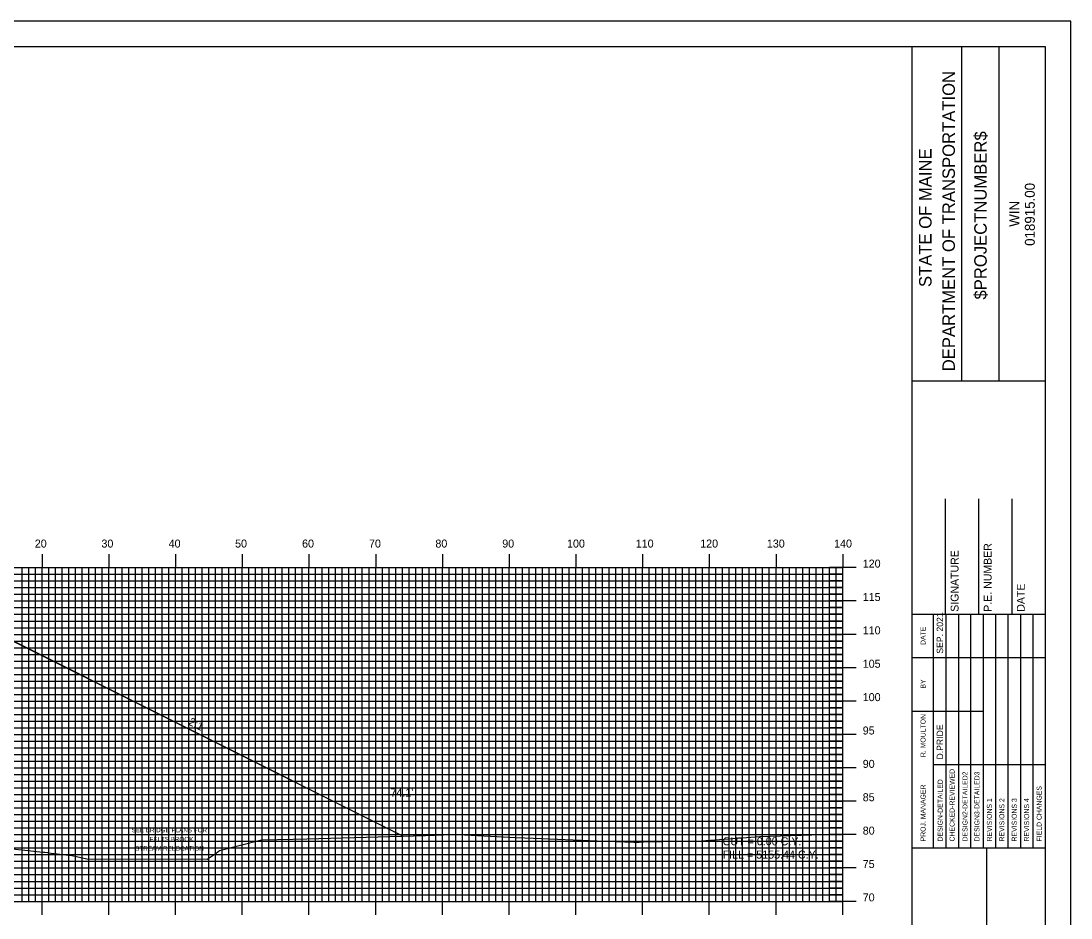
# Model space of a CAD drawing. Extents: x 857897 to 858240, y 364765 to 364985.
# Drawn here: x 858079.7 to 858237, y 364850.8 to 364985.2 of the extents above; entities that cross this region are included whole.
import ezdxf

# ---------------------------------------------------------------- set-up
doc = ezdxf.new("R2010")
doc.units = 0
for name, color, linetype in [('ANNOTATION', 7, 'Continuous'), ('BORDER', 7, 'Continuous'), ('D_Roadway_Centerline', 7, 'Continuous'), ('D_Roadway_SlopeLines', 7, 'Continuous'), ('D_Text_Standard', 7, 'Continuous'), ('H_V ANNOTATION', 7, 'Continuous'), ('MAJOR', 7, 'Continuous'), ('MINOR', 7, 'Continuous'), ('PLOT BOUNDARY', 7, 'Continuous'), ('S_Roadway_Centerline', 7, 'Continuous')]:
    doc.layers.add(name, color=color, linetype=linetype)

msp = doc.modelspace()

# ---------------------------------------------------------------- linework, layer by layer
at = {"layer": 'BORDER'}
for p, q in [((858213.22, 364771.3), (858213.22, 364981.3)), ((858220.68, 364931.3), (858220.68, 364981.3)), ((858226.27, 364931.3), (858226.27, 364981.3)), ((858213.22, 364931.29), (858233.22, 364931.29)), ((858218.22, 364896.31), (858218.22, 364913.6)), ((858223.22, 364896.31), (858223.22, 364913.6)), ((858228.22, 364896.31), (858228.22, 364913.6)), ((858213.22, 364896.31), (858233.22, 364896.31)), ((858213.22, 364861.31), (858233.22, 364861.31)), ((858224.4, 364791.31), (858224.4, 364861.31))]:
    msp.add_line(p, q, dxfattribs=at)
msp.add_lwpolyline([(857913.22, 364771.3), (858233.22, 364771.3), (858233.22, 364981.3), (857913.22, 364981.3)], close=True, dxfattribs=at)
for points in [[(858216.45, 364889.81), (858216.45, 364896.31)], [(858218.32, 364861.31), (858218.32, 364896.31)], [(858220.18, 364896.31), (858220.18, 364861.31)], [(858222.04, 364861.31), (858222.04, 364896.31)], [(858223.91, 364861.31), (858223.91, 364896.31)], [(858225.77, 364861.31), (858225.77, 364896.31)], [(858227.63, 364861.31), (858227.63, 364896.31)], [(858229.5, 364861.31), (858229.5, 364896.31)], [(858231.36, 364861.31), (858231.36, 364896.31)], [(858216.45, 364861.31), (858216.45, 364894.9)], [(858213.22, 364889.81), (858233.22, 364889.81)], [(858213.22, 364881.81), (858216.45, 364881.81)], [(858216.45, 364881.81), (858223.9, 364881.81)], [(858216.45, 364873.81), (858233.22, 364873.81)]]:
    msp.add_lwpolyline(points, dxfattribs=at)
at = {"layer": 'D_Roadway_Centerline'}
msp.add_lwpolyline([(857981.97, 364866.56), (858035.61, 364893.37), (858040.82, 364895.98), (858043.82, 364896.04), (858048.82, 364896.14), (858062.82, 364895.3), (858070.82, 364894.82), (858073.82, 364894.64), (858079.5, 364891.8), (858136.93, 364863.09)], dxfattribs=at)
at = {"layer": 'D_Roadway_SlopeLines'}
msp.add_lwpolyline([(858073.82, 364894.64), (858136.93, 364863.09)], dxfattribs=at)
at = {"layer": 'MAJOR'}
for p, q in [((858082.82, 364905.31), (858082.82, 364903.3)), ((858092.82, 364905.31), (858092.82, 364903.3)), ((858102.82, 364905.31), (858102.82, 364903.3)), ((858112.82, 364905.31), (858112.82, 364903.3)), ((858122.82, 364905.31), (858122.82, 364903.3)), ((858132.82, 364905.31), (858132.82, 364903.3)), ((858142.82, 364905.31), (858142.82, 364903.3)), ((858152.82, 364905.31), (858152.82, 364903.3)), ((858162.82, 364905.31), (858162.82, 364903.3)), ((858172.82, 364905.31), (858172.82, 364903.3)), ((858182.82, 364905.31), (858182.82, 364903.3)), ((858192.82, 364905.31), (858192.82, 364903.3)), ((858202.82, 364905.31), (858202.82, 364903.3)), ((857922.82, 364903.3), (858202.82, 364903.3)), ((857922.82, 364903.3), (858202.82, 364903.3)), ((858082.82, 364853.3), (858082.82, 364903.3)), ((858092.82, 364853.3), (858092.82, 364903.3)), ((858102.82, 364853.3), (858102.82, 364903.3)), ((858112.82, 364853.3), (858112.82, 364903.3)), ((858122.82, 364853.3), (858122.82, 364903.3)), ((858132.82, 364853.3), (858132.82, 364903.3)), ((858142.82, 364853.3), (858142.82, 364903.3)), ((858152.82, 364853.3), (858152.82, 364903.3)), ((858162.82, 364853.3), (858162.82, 364903.3)), ((858172.82, 364853.3), (858172.82, 364903.3)), ((858182.82, 364853.3), (858182.82, 364903.3)), ((858192.82, 364853.3), (858192.82, 364903.3)), ((858204.82, 364903.3), (858200.82, 364903.3)), ((858202.82, 364853.3), (858202.82, 364903.3)), ((858202.82, 364853.3), (858202.82, 364903.3)), ((857922.82, 364898.3), (858202.82, 364898.3)), ((858204.82, 364898.3), (858200.82, 364898.3)), ((857922.82, 364893.3), (858202.82, 364893.3)), ((858204.82, 364893.3), (858200.82, 364893.3)), ((857922.82, 364888.3), (858202.82, 364888.3)), ((858204.82, 364888.3), (858200.82, 364888.3)), ((857922.82, 364883.3), (858202.82, 364883.3)), ((858204.82, 364883.3), (858200.82, 364883.3)), ((857922.82, 364878.3), (858202.82, 364878.3)), ((858204.82, 364878.3), (858200.82, 364878.3)), ((857922.82, 364873.3), (858202.82, 364873.3)), ((858204.82, 364873.3), (858200.82, 364873.3)), ((857922.82, 364868.3), (858202.82, 364868.3)), ((858204.82, 364868.3), (858200.82, 364868.3)), ((857922.82, 364863.3), (858202.82, 364863.3)), ((858204.82, 364863.3), (858200.82, 364863.3)), ((857922.82, 364858.3), (858202.82, 364858.3)), ((858204.82, 364858.3), (858200.82, 364858.3)), ((857922.82, 364853.3), (858202.82, 364853.3)), ((857922.82, 364853.3), (858202.82, 364853.3)), ((858082.82, 364851.3), (858082.82, 364853.3)), ((858092.82, 364851.3), (858092.82, 364853.3)), ((858102.82, 364851.3), (858102.82, 364853.3)), ((858112.82, 364851.3), (858112.82, 364853.3)), ((858122.82, 364851.3), (858122.82, 364853.3)), ((858132.82, 364851.3), (858132.82, 364853.3)), ((858142.82, 364851.3), (858142.82, 364853.3)), ((858152.82, 364851.3), (858152.82, 364853.3)), ((858162.82, 364851.3), (858162.82, 364853.3)), ((858172.82, 364851.3), (858172.82, 364853.3)), ((858182.82, 364851.3), (858182.82, 364853.3)), ((858192.82, 364851.3), (858192.82, 364853.3)), ((858204.82, 364853.3), (858200.82, 364853.3)), ((858202.82, 364851.3), (858202.82, 364853.3))]:
    msp.add_line(p, q, dxfattribs=at)
at = {"layer": 'MINOR'}
for p, q in [((858079.82, 364853.3), (858079.82, 364903.3)), ((858080.82, 364853.3), (858080.82, 364903.3)), ((858081.82, 364853.3), (858081.82, 364903.3)), ((858083.82, 364853.3), (858083.82, 364903.3)), ((858084.82, 364853.3), (858084.82, 364903.3)), ((858085.82, 364853.3), (858085.82, 364903.3)), ((858086.82, 364853.3), (858086.82, 364903.3)), ((858087.82, 364853.3), (858087.82, 364903.3)), ((858088.82, 364853.3), (858088.82, 364903.3)), ((858089.82, 364853.3), (858089.82, 364903.3)), ((858090.82, 364853.3), (858090.82, 364903.3)), ((858091.82, 364853.3), (858091.82, 364903.3)), ((858093.82, 364853.3), (858093.82, 364903.3)), ((858094.82, 364853.3), (858094.82, 364903.3)), ((858095.82, 364853.3), (858095.82, 364903.3)), ((858096.82, 364853.3), (858096.82, 364903.3)), ((858097.82, 364853.3), (858097.82, 364903.3)), ((858098.82, 364853.3), (858098.82, 364903.3)), ((858099.82, 364853.3), (858099.82, 364903.3)), ((858100.82, 364853.3), (858100.82, 364903.3)), ((858101.82, 364853.3), (858101.82, 364903.3)), ((858103.82, 364853.3), (858103.82, 364903.3)), ((858104.82, 364853.3), (858104.82, 364903.3)), ((858105.82, 364853.3), (858105.82, 364903.3)), ((858106.82, 364853.3), (858106.82, 364903.3)), ((858107.82, 364853.3), (858107.82, 364903.3)), ((858108.82, 364853.3), (858108.82, 364903.3)), ((858109.82, 364853.3), (858109.82, 364903.3)), ((858110.82, 364853.3), (858110.82, 364903.3)), ((858111.82, 364853.3), (858111.82, 364903.3)), ((858113.82, 364853.3), (858113.82, 364903.3)), ((858114.82, 364853.3), (858114.82, 364903.3)), ((858115.82, 364853.3), (858115.82, 364903.3)), ((858116.82, 364853.3), (858116.82, 364903.3)), ((858117.82, 364853.3), (858117.82, 364903.3)), ((858118.82, 364853.3), (858118.82, 364903.3)), ((858119.82, 364853.3), (858119.82, 364903.3)), ((858120.82, 364853.3), (858120.82, 364903.3)), ((858121.82, 364853.3), (858121.82, 364903.3)), ((858123.82, 364853.3), (858123.82, 364903.3)), ((858124.82, 364853.3), (858124.82, 364903.3)), ((858125.82, 364853.3), (858125.82, 364903.3)), ((858126.82, 364853.3), (858126.82, 364903.3)), ((858127.82, 364853.3), (858127.82, 364903.3)), ((858128.82, 364853.3), (858128.82, 364903.3)), ((858129.82, 364853.3), (858129.82, 364903.3)), ((858130.82, 364853.3), (858130.82, 364903.3)), ((858131.82, 364853.3), (858131.82, 364903.3)), ((858133.82, 364853.3), (858133.82, 364903.3)), ((858134.82, 364853.3), (858134.82, 364903.3)), ((858135.82, 364853.3), (858135.82, 364903.3)), ((858136.82, 364853.3), (858136.82, 364903.3)), ((858137.82, 364853.3), (858137.82, 364903.3)), ((858138.82, 364853.3), (858138.82, 364903.3)), ((858139.82, 364853.3), (858139.82, 364903.3)), ((858140.82, 364853.3), (858140.82, 364903.3)), ((858141.82, 364853.3), (858141.82, 364903.3)), ((858143.82, 364853.3), (858143.82, 364903.3)), ((858144.82, 364853.3), (858144.82, 364903.3)), ((858145.82, 364853.3), (858145.82, 364903.3)), ((858146.82, 364853.3), (858146.82, 364903.3)), ((858147.82, 364853.3), (858147.82, 364903.3)), ((858148.82, 364853.3), (858148.82, 364903.3)), ((858149.82, 364853.3), (858149.82, 364903.3)), ((858150.82, 364853.3), (858150.82, 364903.3)), ((858151.82, 364853.3), (858151.82, 364903.3)), ((858153.82, 364853.3), (858153.82, 364903.3)), ((858154.82, 364853.3), (858154.82, 364903.3)), ((858155.82, 364853.3), (858155.82, 364903.3)), ((858156.82, 364853.3), (858156.82, 364903.3)), ((858157.82, 364853.3), (858157.82, 364903.3)), ((858158.82, 364853.3), (858158.82, 364903.3)), ((858159.82, 364853.3), (858159.82, 364903.3)), ((858160.82, 364853.3), (858160.82, 364903.3)), ((858161.82, 364853.3), (858161.82, 364903.3)), ((858163.82, 364853.3), (858163.82, 364903.3)), ((858164.82, 364853.3), (858164.82, 364903.3)), ((858165.82, 364853.3), (858165.82, 364903.3)), ((858166.82, 364853.3), (858166.82, 364903.3)), ((858167.82, 364853.3), (858167.82, 364903.3)), ((858168.82, 364853.3), (858168.82, 364903.3)), ((858169.82, 364853.3), (858169.82, 364903.3)), ((858170.82, 364853.3), (858170.82, 364903.3)), ((858171.82, 364853.3), (858171.82, 364903.3)), ((858173.82, 364853.3), (858173.82, 364903.3)), ((858174.82, 364853.3), (858174.82, 364903.3)), ((858175.82, 364853.3), (858175.82, 364903.3)), ((858176.82, 364853.3), (858176.82, 364903.3)), ((858177.82, 364853.3), (858177.82, 364903.3)), ((858178.82, 364853.3), (858178.82, 364903.3)), ((858179.82, 364853.3), (858179.82, 364903.3)), ((858180.82, 364853.3), (858180.82, 364903.3)), ((858181.82, 364853.3), (858181.82, 364903.3)), ((858183.82, 364853.3), (858183.82, 364903.3)), ((858184.82, 364853.3), (858184.82, 364903.3)), ((858185.82, 364853.3), (858185.82, 364903.3)), ((858186.82, 364853.3), (858186.82, 364903.3)), ((858187.82, 364853.3), (858187.82, 364903.3)), ((858188.82, 364853.3), (858188.82, 364903.3)), ((858189.82, 364853.3), (858189.82, 364903.3)), ((858190.82, 364853.3), (858190.82, 364903.3)), ((858191.82, 364853.3), (858191.82, 364903.3)), ((858193.82, 364853.3), (858193.82, 364903.3)), ((858194.82, 364853.3), (858194.82, 364903.3)), ((858195.82, 364853.3), (858195.82, 364903.3)), ((858196.82, 364853.3), (858196.82, 364903.3)), ((858197.82, 364853.3), (858197.82, 364903.3)), ((858198.82, 364853.3), (858198.82, 364903.3)), ((858199.82, 364853.3), (858199.82, 364903.3)), ((858200.82, 364853.3), (858200.82, 364903.3)), ((858201.82, 364853.3), (858201.82, 364903.3)), ((857922.82, 364902.3), (858202.82, 364902.3)), ((857922.82, 364901.3), (858202.82, 364901.3)), ((858202.82, 364902.3), (858200.82, 364902.3)), ((858202.82, 364901.3), (858200.82, 364901.3)), ((857922.82, 364900.3), (858202.82, 364900.3)), ((858202.82, 364900.3), (858200.82, 364900.3)), ((857922.82, 364899.3), (858202.82, 364899.3)), ((858202.82, 364899.3), (858200.82, 364899.3)), ((857922.82, 364897.3), (858202.82, 364897.3)), ((857922.82, 364896.3), (858202.82, 364896.3)), ((858202.82, 364897.3), (858200.82, 364897.3)), ((858202.82, 364896.3), (858200.82, 364896.3)), ((857922.82, 364895.3), (858202.82, 364895.3)), ((858202.82, 364895.3), (858200.82, 364895.3)), ((857922.82, 364894.3), (858202.82, 364894.3)), ((858202.82, 364894.3), (858200.82, 364894.3)), ((857922.82, 364892.3), (858202.82, 364892.3)), ((858202.82, 364892.3), (858200.82, 364892.3)), ((857922.82, 364891.3), (858202.82, 364891.3)), ((857922.82, 364890.3), (858202.82, 364890.3)), ((858202.82, 364891.3), (858200.82, 364891.3)), ((858202.82, 364890.3), (858200.82, 364890.3)), ((857922.82, 364889.3), (858202.82, 364889.3)), ((858202.82, 364889.3), (858200.82, 364889.3)), ((857922.82, 364887.3), (858202.82, 364887.3)), ((858202.82, 364887.3), (858200.82, 364887.3)), ((857922.82, 364886.3), (858202.82, 364886.3)), ((857922.82, 364885.3), (858202.82, 364885.3)), ((858202.82, 364886.3), (858200.82, 364886.3)), ((858202.82, 364885.3), (858200.82, 364885.3)), ((857922.82, 364884.3), (858202.82, 364884.3)), ((858202.82, 364884.3), (858200.82, 364884.3)), ((857922.82, 364882.3), (858202.82, 364882.3)), ((858202.82, 364882.3), (858200.82, 364882.3)), ((857922.82, 364881.3), (858202.82, 364881.3)), ((858202.82, 364881.3), (858200.82, 364881.3)), ((857922.82, 364880.3), (858202.82, 364880.3)), ((857922.82, 364879.3), (858202.82, 364879.3)), ((858202.82, 364880.3), (858200.82, 364880.3)), ((858202.82, 364879.3), (858200.82, 364879.3)), ((857922.82, 364877.3), (858202.82, 364877.3)), ((857922.82, 364876.3), (858202.82, 364876.3)), ((858202.82, 364877.3), (858200.82, 364877.3)), ((858202.82, 364876.3), (858200.82, 364876.3)), ((857922.82, 364875.3), (858202.82, 364875.3)), ((857922.82, 364874.3), (858202.82, 364874.3)), ((858202.82, 364875.3), (858200.82, 364875.3)), ((858202.82, 364874.3), (858200.82, 364874.3)), ((857922.82, 364872.3), (858202.82, 364872.3)), ((857922.82, 364871.3), (858202.82, 364871.3)), ((858202.82, 364872.3), (858200.82, 364872.3)), ((858202.82, 364871.3), (858200.82, 364871.3)), ((857922.82, 364870.3), (858202.82, 364870.3)), ((858202.82, 364870.3), (858200.82, 364870.3)), ((857922.82, 364869.3), (858202.82, 364869.3)), ((858202.82, 364869.3), (858200.82, 364869.3)), ((857922.82, 364867.3), (858202.82, 364867.3)), ((858202.82, 364867.3), (858200.82, 364867.3)), ((857922.82, 364866.3), (858202.82, 364866.3)), ((857922.82, 364865.3), (858202.82, 364865.3)), ((858202.82, 364866.3), (858200.82, 364866.3)), ((858202.82, 364865.3), (858200.82, 364865.3)), ((857922.82, 364864.3), (858202.82, 364864.3)), ((858202.82, 364864.3), (858200.82, 364864.3)), ((857922.82, 364862.3), (858202.82, 364862.3)), ((858202.82, 364862.3), (858200.82, 364862.3)), ((857922.82, 364861.3), (858202.82, 364861.3)), ((857922.82, 364860.3), (858202.82, 364860.3)), ((858202.82, 364861.3), (858200.82, 364861.3)), ((858202.82, 364860.3), (858200.82, 364860.3)), ((857922.82, 364859.3), (858202.82, 364859.3)), ((858202.82, 364859.3), (858200.82, 364859.3)), ((857922.82, 364857.3), (858202.82, 364857.3)), ((858202.82, 364857.3), (858200.82, 364857.3)), ((857922.82, 364856.3), (858202.82, 364856.3)), ((858202.82, 364856.3), (858200.82, 364856.3)), ((857922.82, 364855.3), (858202.82, 364855.3)), ((857922.82, 364854.3), (858202.82, 364854.3)), ((858202.82, 364855.3), (858200.82, 364855.3)), ((858202.82, 364854.3), (858200.82, 364854.3))]:
    msp.add_line(p, q, dxfattribs=at)
at = {"layer": 'PLOT BOUNDARY'}
msp.add_lwpolyline([(857897.03, 364765.18), (858237.03, 364765.18), (858237.03, 364985.18), (857897.03, 364985.18)], close=True, dxfattribs=at)
at = {"layer": 'S_Roadway_Centerline'}
msp.add_lwpolyline([(858070.62, 364862.03), (858082.49, 364860.71), (858083.02, 364860.68), (858083.21, 364860.67), (858083.63, 364860.61), (858083.72, 364860.56), (858087.28, 364860.18), (858089.77, 364859.6), (858102.76, 364859.66), (858107.56, 364859.62), (858108.91, 364860.5), (858109.41, 364860.94), (858115.72, 364862.51), (858120.44, 364862.63), (858122.49, 364862.68), (858140.27, 364863.18), (858144.33, 364863.3), (858145.18, 364863.31), (858153.89, 364862.85), (858156.45, 364862.76), (858166.03, 364862.35), (858171.52, 364862.18), (858172.3, 364862.18), (858172.96, 364862.21), (858181.66, 364862.36), (858190.42, 364863.04), (858202.82, 364863.4)], dxfattribs=at)

# ---------------------------------------------------------------- texts
at = {"layer": 'ANNOTATION'}
msp.add_text('2:1', height=1.2, rotation=333.4349, dxfattribs=at).set_placement((858104.65, 364879.82))
for s, p in [('SEE BRIDGE PLANS FOR', (858096.22, 364863.65)), ('FELTS BROOK ', (858098.92, 364862.27)), ('STREAM RELOCATION', (858096.78, 364860.89))]:
    msp.add_text(s, height=0.68, dxfattribs=at).set_placement(p)
at = {"layer": 'BORDER'}
for s, height, p in [('DEPARTMENT OF TRANSPORTATION', 1.8635, (858219.63, 364932.71)), ('$PROJECTNUMBER$', 1.8635, (858224.4, 364943.46)), ('STATE OF MAINE', 1.8635, (858216.13, 364945.33)), ('018915.00', 1.491, (858231.61, 364951.5)), ('WIN', 1.491, (858229.29, 364954.36)), ('SIGNATURE', 1.181, (858220.18, 364896.69)), ('P.E. NUMBER', 1.1811, (858225.14, 364896.69)), ('DATE', 1.181, (858230.1, 364896.69)), ('SEP. 2021', 0.969, (858217.87, 364890.4)), ('DATE', 0.743, (858215.23, 364891.72)), ('BY', 0.743, (858215.23, 364885.18)), ('R. MOULTON', 0.745, (858215.23, 364874.91)), ('D.PRIDE', 0.969, (858217.87, 364874.55)), ('CHECKED-REVIEWED', 0.7455, (858219.58, 364862.28)), ('DESIGN-DETAILED', 0.7455, (858217.79, 364862.28)), ('DESIGN2-DETAILED2', 0.7455, (858221.52, 364862.28)), ('DESIGN3-DETAILED3', 0.7455, (858223.31, 364862.28)), ('PROJ. MANAGER', 0.7455, (858215.23, 364862.28)), ('FIELD CHANGES', 0.7455, (858232.63, 364862.28)), ('REVISIONS 1', 0.7455, (858225.17, 364862.28)), ('REVISIONS 2', 0.7455, (858227.04, 364862.28)), ('REVISIONS 3', 0.7455, (858228.9, 364862.28)), ('REVISIONS 4', 0.7455, (858230.76, 364862.28))]:
    msp.add_text(s, height=height, rotation=90, dxfattribs=at).set_placement(p)
at = {"layer": 'D_Text_Standard'}
for s, p in [("74.1'", (858135.03, 364868.99)), ('CUT = 0.00 C.Y.', (858184.82, 364861.7)), ('FILL = 5155.44 C.Y.', (858184.82, 364859.71))]:
    msp.add_text(s, height=1.2, dxfattribs=at).set_placement(p)
at = {"layer": 'H_V ANNOTATION'}
for s, p in [('20', (858081.73, 364906.3)), ('30', (858091.72, 364906.3)), ('40', (858101.79, 364906.3)), ('50', (858111.75, 364906.3)), ('60', (858121.79, 364906.3)), ('70', (858131.82, 364906.3)), ('80', (858141.77, 364906.3)), ('90', (858151.79, 364906.3)), ('100', (858161.5, 364906.3)), ('110', (858171.8, 364906.3)), ('120', (858181.46, 364906.3)), ('130', (858191.45, 364906.3)), ('140', (858201.53, 364906.3)), ('120', (858205.82, 364903.3)), ('115', (858205.82, 364898.3)), ('110', (858205.82, 364893.3)), ('105', (858205.82, 364888.3)), ('100', (858205.82, 364883.3)), ('95', (858205.82, 364878.3)), ('90', (858205.82, 364873.3)), ('85', (858205.82, 364868.3)), ('80', (858205.82, 364863.3)), ('75', (858205.82, 364858.3)), ('70', (858205.82, 364853.3))]:
    msp.add_text(s, height=1.2, dxfattribs=at).set_placement(p)

doc.saveas('drawing.dxf')
